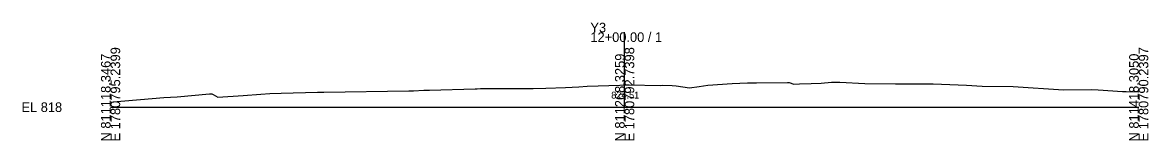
# Model space of a CAD drawing. Extents: x -26 to 303, y -10 to 4017.
# Drawn here: x -25.7 to 302.8, y 2490.3 to 2524.7 of the extents above; entities that cross this region are included whole.
import ezdxf

# ---------------------------------------------------------------- set-up
doc = ezdxf.new("R2010")
doc.units = 0
for name, color, linetype in [('Exist Cross Section Cell', 7, 'Continuous'), ('Exist XS Center Line Elevation Label', 7, 'Continuous'), ('Exist XS Ground Line', 7, 'Continuous')]:
    doc.layers.add(name, color=color, linetype=linetype)

msp = doc.modelspace()

# ---------------------------------------------------------------- linework, layer by layer
at = {"layer": 'Exist Cross Section Cell'}
for p, q in [((150, 2500), (150, 2521.81)), ((0, 2500), (150, 2500)), ((150, 2500), (300, 2500))]:
    msp.add_line(p, q, dxfattribs=at)
at = {"layer": 'Exist XS Ground Line'}
for p, q in [((174.3, 2506.39), (181.39, 2506.87)), ((181.39, 2506.87), (185.89, 2507.05)), ((185.89, 2507.05), (188.46, 2507.1)), ((188.46, 2507.1), (197.54, 2507.17)), ((197.54, 2507.17), (198.03, 2507.21)), ((198.03, 2507.21), (199.36, 2506.75)), ((199.36, 2506.75), (201.02, 2506.81)), ((201.02, 2506.81), (204.41, 2506.9)), ((204.41, 2506.9), (207.36, 2506.96)), ((207.36, 2506.96), (210.36, 2507.27)), ((210.36, 2507.27), (212.77, 2507.25)), ((212.77, 2507.25), (220.05, 2506.92)), ((220.05, 2506.92), (229.03, 2506.83)), ((229.03, 2506.83), (235.31, 2506.77)), ((235.31, 2506.77), (240.06, 2506.77)), ((240.06, 2506.77), (249.73, 2506.4)), ((19.47, 2503.01), (28.91, 2503.88)), ((28.91, 2503.88), (29.52, 2503.9)), ((29.52, 2503.9), (29.97, 2503.68)), ((29.97, 2503.68), (31.28, 2502.91)), ((31.28, 2502.91), (38.69, 2503.44)), ((38.69, 2503.44), (43.83, 2503.81)), ((43.83, 2503.81), (46.42, 2503.97)), ((46.42, 2503.97), (49.8, 2504.09)), ((49.8, 2504.09), (60.4, 2504.33)), ((60.4, 2504.33), (61.83, 2504.34)), ((61.83, 2504.34), (62.25, 2504.34)), ((62.25, 2504.34), (87.02, 2504.75)), ((87.02, 2504.75), (87.72, 2504.76)), ((87.72, 2504.76), (88.42, 2504.78)), ((88.42, 2504.78), (91.45, 2504.92)), ((91.45, 2504.92), (92.04, 2504.95)), ((92.04, 2504.95), (93.01, 2504.95)), ((93.01, 2504.95), (106.37, 2505.39)), ((106.37, 2505.39), (107, 2505.38)), ((107, 2505.38), (107.94, 2505.42)), ((107.94, 2505.42), (111.3, 2505.44)), ((111.3, 2505.44), (123.29, 2505.45)), ((123.29, 2505.45), (126.99, 2505.5)), ((126.99, 2505.5), (132.7, 2505.75)), ((132.7, 2505.75), (136.62, 2505.96)), ((136.62, 2505.96), (139.06, 2506.1)), ((139.06, 2506.1), (148.55, 2506.46)), ((148.55, 2506.46), (149.99, 2506.52)), ((149.99, 2506.52), (151.34, 2506.49)), ((151.34, 2506.49), (160.35, 2506.34)), ((160.35, 2506.34), (160.91, 2506.37)), ((160.91, 2506.37), (163.82, 2506.35)), ((163.82, 2506.35), (165.05, 2506.24)), ((165.05, 2506.24), (168.96, 2505.67)), ((168.96, 2505.67), (171.77, 2506.04)), ((171.77, 2506.04), (174.3, 2506.39)), ((249.73, 2506.4), (254.32, 2506.13)), ((254.32, 2506.13), (263.38, 2506)), ((263.38, 2506), (278, 2505.09)), ((278, 2505.09), (286.14, 2505.11)), ((286.14, 2505.11), (288.18, 2505.01)), ((288.18, 2505.01), (295.26, 2504.61)), ((295.26, 2504.61), (296.36, 2504.59)), ((296.36, 2504.59), (300, 2504.5)), ((0, 2501.47), (0.75, 2501.53)), ((0.75, 2501.53), (15.54, 2502.83)), ((15.54, 2502.83), (19.47, 2503.01))]:
    msp.add_line(p, q, dxfattribs=at)

# ---------------------------------------------------------------- texts
at = {"layer": 'Exist Cross Section Cell'}
for s, p in [('Y3', (140, 2521.81)), ('12+00.00 / 1', (140, 2519.01)), ('EL 818', (-26, 2498.6))]:
    msp.add_text(s, height=2.8, dxfattribs=at).set_placement(p)
for s, p in [('E 1780795.2399', (2.8, 2490)), ('E 1780792.7398', (152.8, 2490)), ('E 1780790.2397', (302.8, 2490)), ('N 811118.3467', (0, 2490)), ('N 811268.3259', (150, 2490)), ('N 811418.3050', (300, 2490))]:
    msp.add_text(s, height=2.8, rotation=90, dxfattribs=at).set_placement(p)
at = {"layer": 'Exist XS Center Line Elevation Label'}
msp.add_text('824.51', height=2, dxfattribs=at).set_placement((146.08, 2502.51))

doc.saveas('drawing.dxf')
